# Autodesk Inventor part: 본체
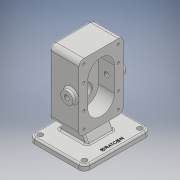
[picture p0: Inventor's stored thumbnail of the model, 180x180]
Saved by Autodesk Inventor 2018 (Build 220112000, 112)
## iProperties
Created: 2020-04
Part Number: 본체
Material: 일반
Document SubType Name: Modeling
Designer: USER
Density: 1 g/cm^3
Appearance: 기본값
Author: USER
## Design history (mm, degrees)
sketch "스케치1"
  geometry: L1 (0, 0)-(80, 0); L2 (80, 0)-(80, 120); L3 (80, 120)-(0, 120); L4 (0, 120)-(0, 0)
  constraints: 8 end point, 2 parallel, 1 horizontal, 1 perpendicular
  dimensions: "d0" = 80 distance of L2.end L3.end; "d1" = 120 distance of L3.end L1.start
extrude "돌출1" new body sketch "스케치1" distance "d2" = 53; taper "d3" = 0 deg
node "작업 평면1"
sketch "스케치3"
  geometry: L1 (-82, 40)-(-38, 40); L2 (-82, 16)-(-38, 16); L3 (-38, 64)-(-82, 64); L4 (-120, 80)-(-120, 0) reference; L5 (-120, 0)-(0, 0) reference; A1 r 24 centre (-82, 40) between (-82, 64) and (-82, 16); A2 r 24 centre (-38, 40) between (-38, 16) and (-38, 64); 4 further points
  constraints: 8 end point, 5 point on circle, 4 tangent, 3 midpoint, 2 centre point, 1 horizontal, 1 horizontal alignment, 1 parallel, 1 vertical alignment
  dimensions: "d9" = 24 radius of A1; "d10" = 22 distance of L1.start point (-60, 40)
extrude "돌출3" cut sketch "스케치3" distance "d11" = 29; taper "d12" = 0 deg
sketch "스케치4"
  geometry: C1 r 12.5 at (-82, 40); C2 r 12.5 at (-38, 40); A1 r 24 centre (-82, 40) between (-82, 64) and (-82, 16) reference; A2 r 24 centre (-38, 40) between (-38, 16) and (-38, 64) reference; 1 further point
  constraints: 2 centre point, 2 concentric
  dimensions: "d13" = 25 diameter of C1; "d14" = 25 diameter of C2
extrude "돌출4" cut sketch "스케치4" distance "d15" = 15; taper "d16" = 0 deg
sketch "스케치5"
  geometry: C1 r 19 at (82, 40); C2 r 12.5 at (82, 40) reference; A1 r 24 centre (82, 40) between (82, 16) and (82, 64) reference; 1 further point
  constraints: 2 concentric, 1 centre point
  dimensions: "d17" = 38 diameter of C1
extrude "돌출5" join sketch "스케치5" distance "d18" = 17; taper "d19" = 0 deg
sketch "스케치6"
  geometry: C1 r 14 at (0, 0); C2 r 19 at (0, 0) reference; 1 further point
  constraints: 1 centre point, 1 concentric
  dimensions: "d20" = 28 diameter of C1
extrude "돌출6" cut sketch "스케치6" distance "d21" = 7.3; taper "d22" = 0 deg
sketch "스케치7"
  geometry: C1 r 8.5 at (0, 0); C2 r 14 at (0, 0) reference; 1 further point
  constraints: 1 centre point, 1 coincident
  dimensions: "d23" = 17 diameter of C1
extrude "돌출7" cut sketch "스케치7" extent not by distance; stored distance "d24" = 7.3; taper "d25" = 0 deg
sketch "스케치8"
  geometry: L1 (0, 0)-(53, 0) reference; L2 (53, 120)-(53, 0) reference; C1 r 11 at (39, 60); 2 further points
  constraints: 1 centre point, 1 horizontal alignment, 1 midpoint
  dimensions: "d26" = 22 diameter of C1; "d29" = 14 distance from line of L2 C1.centre
extrude "돌출8" join sketch "스케치8" distance "d27" = 8; taper "d28" = 0 deg
sketch "스케치9"
  geometry: C1 r 11 at (0, 0) reference; 2 further points
  constraints: 1 coincident
hole "구멍1" sketch "스케치9" at (0, 0) diameter "d30" = 8.917; stored, may be unused: countersink angle "d34" = 90 deg, drill point angle "d36" = 118 deg; dims "d31" = 20, "d32" = 4, "d33" = 2, "d35" = 25.1
node "작업 평면2"
node "작업 평면3"
sketch "스케치12"
  geometry: L1 (0, 80)-(-120, 80) reference; C1 r 8.5 at (-82, 40) reference; C2 r 12.5 at (-38, 40) reference; 9 further points
  constraints: 6 horizontal alignment, 6 vertical alignment
  dimensions: "d43" = 102 distance of point (-9, 71) point (-111, 71); "d44" = 29 distance of point (-82, 71) point (-111, 71); "d45" = 62 distance of point (-111, 9) point (-111, 71); "d46" = 9 distance from line of point (-111, 71) L1
hole "구멍2" sketch "스케치12" at (-111, 9), (-82, 9), (-38, 9), (-9, 9), (-9, 71), (-38, 71), (-82, 71), (-111, 71) diameter "d47" = 4.134; stored, may be unused: countersink angle "d51" = 90 deg, drill point angle "d53" = 118 deg; dims "d48" = 10, "d49" = 4, "d50" = 2, "d52" = 12
fillet "모깎기1" dims "d65" = 9
node "작업 평면4"
sketch "스케치14"
  geometry: L1 (-17, 50)-(-17, 12) reference; L2 (-17, 91)-(83, 91); L3 (83, 91)-(83, -29); L4 (83, -29)-(-17, -29); L5 (-17, -29)-(-17, 91); L6 (53, 0)-(53, 62) reference; 3 further points
  constraints: 8 end point, 2 midpoint, 2 parallel, 1 horizontal, 1 horizontal alignment, 1 perpendicular, 1 point on line
  dimensions: "d69" = 100 distance of L2.start L2.end; "d70" = 120 distance of L2.end L3.end
extrude "돌출10" join sketch "스케치14" distance "d71" = 10; taper "d72" = 0 deg
node "작업 평면5"
sketch "스케치15"
  geometry: L1 (70, -10)-(53.698, -38.236); L2 (0, -10)-(100, -10) reference; L3 (17, -10)-(33.302, -38.236); L4 (0, 0)-(0, -10) reference; L5 (70, -10)-(17, -10); L6 (33.302, -38.236)-(53.698, -38.236); L7 (70, -39)-(17, -39) reference; 1 further point
  constraints: 8 end point, 2 point on line, 1 horizontal, 1 parallel
  dimensions: "d73" = 17 distance from line of L4 L3.start; "d74" = 53 distance of L3.start L1.start; "d75" = 60 deg angle of L2 L3; "d76" = 60 deg angle of L2 L1
extrude "돌출11" join sketch "스케치15" stored distance "d77" = 48; taper "d78" = 0 deg
sketch "스케치16"
  geometry: L1 (83, -29)-(83, 91) reference; L2 (-17, -29)-(83, -29) reference; L3 (-17, 91)-(-17, -29) reference; L4 (83, 91)-(-17, 91) reference; 5 further points
  constraints: 2 horizontal alignment, 2 vertical alignment
  dimensions: "d79" = 10 distance from line of L1 point (73, -19); "d80" = 10 distance from line of L2 point (73, -19); "d81" = 10 distance from line of L3 point (-7, -19); "d82" = 10 distance from line of L4 point (-7, 81)
hole "구멍4" sketch "스케치16" at (73, -19), (-7, -19), (-7, 81), (73, 81) diameter "d83" = 9; stored, may be unused: countersink angle "d87" = 90 deg, drill point angle "d89" = 118 deg; dims "d84" = 10, "d85" = 4, "d86" = 2, "d88" = 12
fillet "모깎기2" dims "d90" = 10
fillet "모깎기3" dims "d91" = 3
fillet "모깎기4" dims "d92" = 3
fillet "모깎기5" dims "d93" = 3
chamfer "모따기2" distance "d97" = 1; stored, may be unused: second distance "d98" = 2, angle "d99" = 45 deg
chamfer "모따기3" distance "d100" = 1; stored, may be unused: second distance "d101" = 2, angle "d102" = 45 deg
fillet "모깎기6" dims "d103" = 3
sketch "스케치17"
  geometry: L1 (-7, -29)-(73, -29) reference; L2 (83, -19)-(83, 81) reference; 2 further points
  constraints: 1 other
  dimensions: "d104" = 60 distance from line of L1 point (73, 31); "d105" = 10 distance from line of L2 point (73, 31)
feature "엠보싱1" sketch "스케치17" dims "d0" = 80, "d1" = 120, "d106" = 0.5, "d107" = 0
fillet "모깎기9" dims "d110" = 0.5
chamfer "모따기4" distance "d111" = 0.7; stored, may be unused: second distance "d112" = 2, angle "d113" = 30 deg
node "솔리드1"
mirror "미러1"
node "투영된 루프1"
